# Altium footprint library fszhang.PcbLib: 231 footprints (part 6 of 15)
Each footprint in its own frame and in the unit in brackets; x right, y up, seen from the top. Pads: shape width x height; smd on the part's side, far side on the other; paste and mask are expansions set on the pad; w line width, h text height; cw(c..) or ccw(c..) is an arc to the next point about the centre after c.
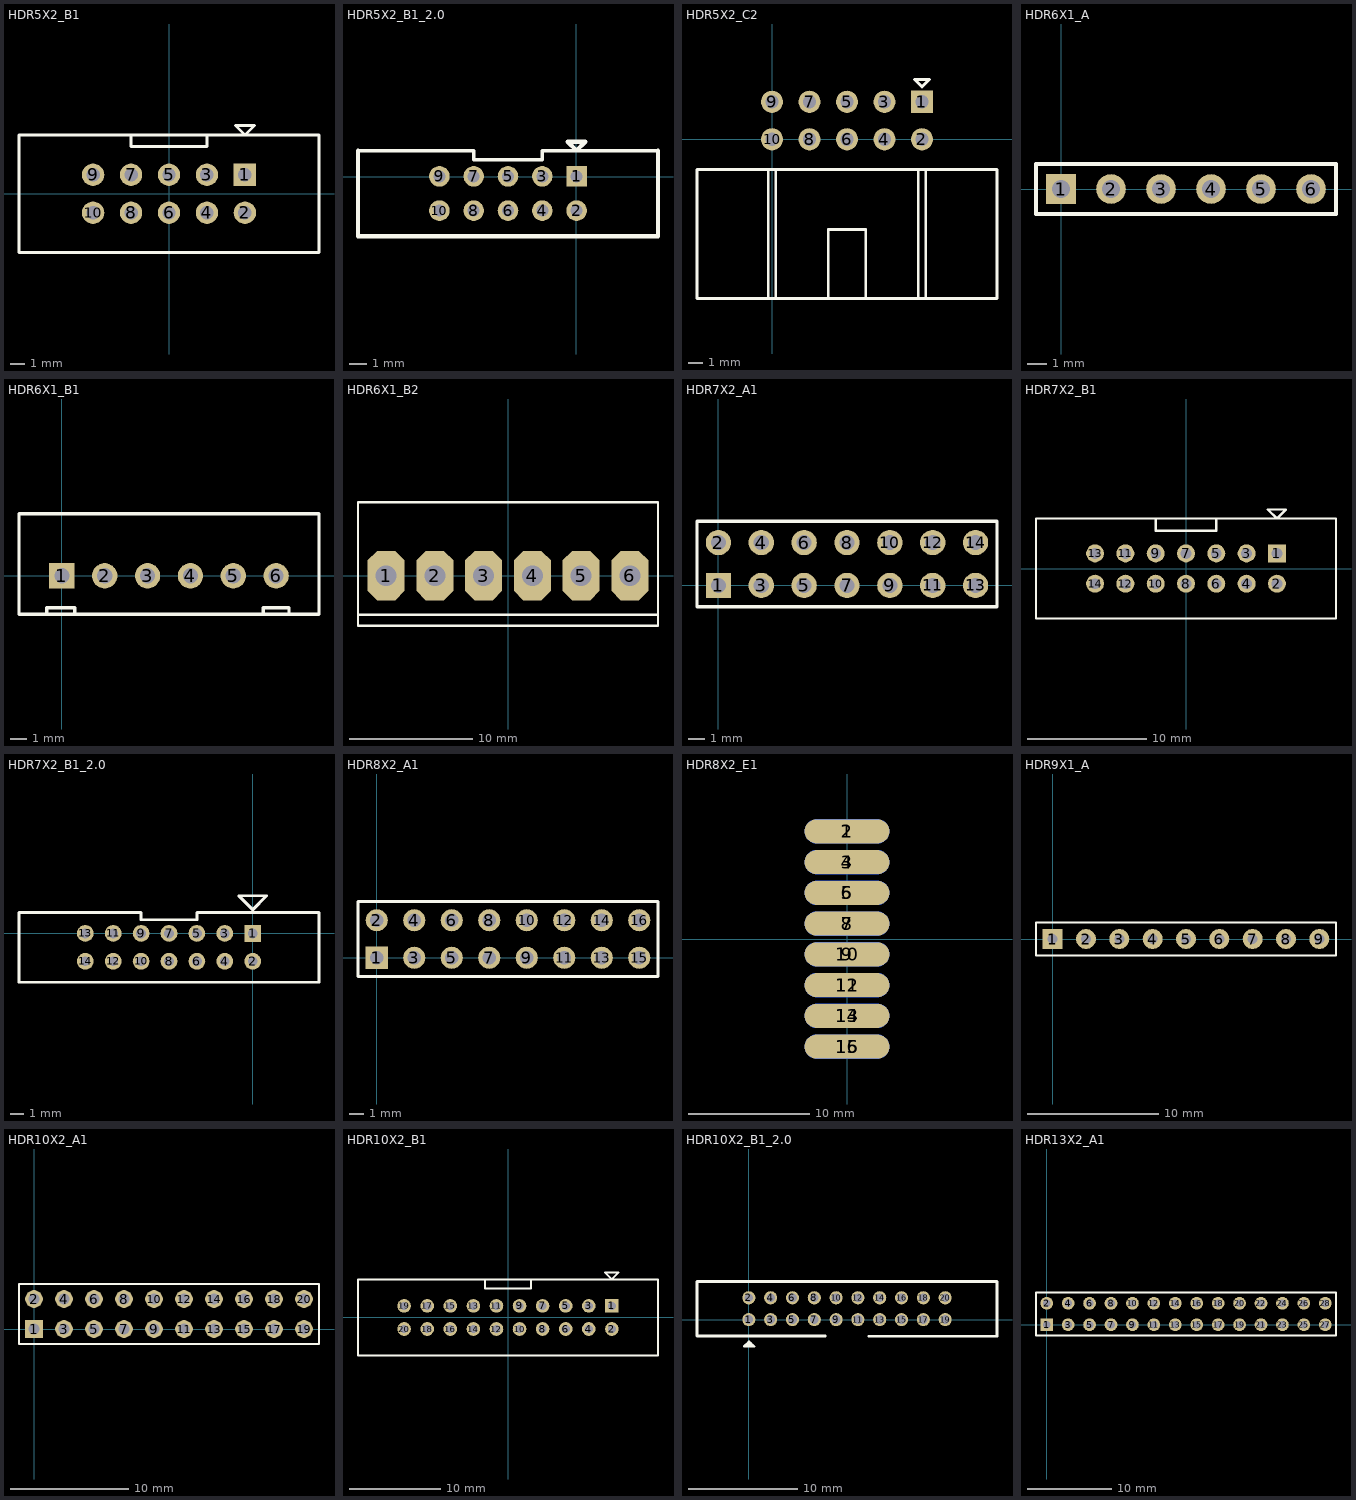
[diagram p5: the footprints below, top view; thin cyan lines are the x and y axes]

## HDR5X2_B1 [mm] "Connector; Header; 5x2 Position"
height 1.2
pads (10):
  rect 1.5x1.5 hole 0.9: 1(5.08,1.27)
  round 1.5 hole 0.9: 2(5.08,-1.27) 3(2.54,1.27) 4(2.54,-1.27) 5(0,1.27) 6(0,-1.27) 7(-2.54,1.27) 8(-2.54,-1.27) 9(-5.08,1.27) 10(-5.08,-1.27)
Top Overlay:
  lines w0.2: -2.54,3.937 -2.54,3.175 2.54,3.175 2.54,3.937 ; -10.033,-3.937 10.033,-3.937 10.033,3.937 -10.033,3.937 -10.033,-3.937 ; 4.445,4.572 5.588,4.572 5.715,4.572 5.08,3.937 4.445,4.572

## HDR5X2_B1_2.0 [mm]
pads (10):
  rect 1.2x1.2 hole 0.7: 1(0.006,0.012)
  round 1.2 hole 0.7: 2(0.006,-1.988) 3(-1.994,0.012) 4(-1.994,-1.988) 5(-3.994,0.012) 6(-3.994,-1.988) 7(-5.994,0.012) 8(-5.994,-1.988) 9(-7.994,0.012) 10(-7.994,-1.988)
Top Overlay:
  lines w0.2: -12.744,1.512 -5.994,1.512 -5.994,0.987 -1.994,0.987 -1.994,1.512 4.756,1.512
  lines w0.254: -12.744,1.512 -12.744,-3.488 4.756,-3.488 4.756,1.512 ; -0.508,2.032 0.508,2.032 0,1.524 -0.508,2.032

## HDR5X2_C2 [mm]
height 1.75
pads (10):
  rect 1.5x1.5 hole 0.9: 1(10.16,2.54)
  round 1.5 hole 0.9: 2(10.16,0) 3(7.62,2.54) 4(7.62,0) 5(5.08,2.54) 6(5.08,0) 7(2.54,2.54) 8(2.54,0) 9(0,2.54) 10(0,0)
Top Overlay:
  lines w0.2: -0.254,-10.795 -0.254,-2.032 ; 0.254,-10.795 0.254,-2.032 ; 3.81,-10.795 3.81,-6.096 6.35,-6.096 6.35,-10.795 ; 9.906,-10.795 9.906,-2.032 ; 10.414,-10.795 10.414,-2.032 ; -5.08,-10.795 -5.08,-2.032 15.24,-2.032 15.24,-10.795 -5.08,-10.795 ; 9.652,4.064 10.541,4.064 10.668,4.064 10.16,3.556 9.652,4.064

## HDR6X1_A [mm] "Connector; Header; 4 Position"
height 1.6
pads (6):
  rect 1.5x1.5 hole 0.9: 1(0,0)
  round 1.5 hole 0.9: 2(2.54,0) 3(5.08,0) 4(7.62,0) 5(10.16,0) 6(12.7,0)
Top Overlay:
  lines w0.2: -1.27,-1.27 -1.27,1.27 13.97,1.27 13.97,-1.27 -1.27,-1.27

## HDR6X1_B1 [mm] "Connector; Header; 4 Position"
height 1.6
pads (6):
  rect 1.5x1.5 hole 0.9: 1(0,0)
  round 1.5 hole 0.9: 2(2.54,0) 3(5.08,0) 4(7.62,0) 5(10.16,0) 6(12.7,0)
Top Overlay:
  lines w0.2: -0.889,-2.286 -0.889,-1.905 0.762,-1.905 0.762,-2.286 ; 11.938,-2.286 11.938,-1.905 13.462,-1.905 13.462,-2.286 ; -2.54,-2.286 15.24,-2.286 15.24,3.683 -2.54,3.683 -2.54,-2.286
3D body: height 1.5, standoff 0, extent -2.413,-2.159 15.24,3.556

## HDR6X1_B2 [mm] "Connector; Header; 3 Position"
height 1.5
pads (6):
  oct 3x4 hole 1.7: 1(-9.906,0) 2(-5.944,0) 3(-1.981,0) 4(1.981,0) 5(5.944,0) 6(9.906,0)
Top Overlay:
  lines w0.2: -12.192,-3.175 12.192,-3.175 ; -2.54,-4.064 2.54,-4.064 ; -12.192,-4.064 -12.192,5.969 12.192,5.969 12.192,-4.064 -12.192,-4.064

## HDR7X2_A1 [mm] "Connector; Header; 7x2 Position"
height 1.75
pads (14):
  rect 1.5x1.5 hole 0.9: 1(0,0)
  round 1.5 hole 0.9: 2(0,2.54) 3(2.54,0) 4(2.54,2.54) 5(5.08,0) 6(5.08,2.54) 7(7.62,0) 8(7.62,2.54) 9(10.16,0) 10(10.16,2.54) 11(12.7,0) 12(12.7,2.54) 13(15.24,0) 14(15.24,2.54)
Top Overlay:
  lines w0.2: -1.27,-1.27 -1.27,3.81 16.51,3.81 16.51,-1.27 -1.27,-1.27

## HDR7X2_B1 [mm] "Connector"
height 2.65
pads (14):
  rect 1.5x1.5 hole 0.9: 1(7.62,1.27)
  round 1.5 hole 0.9: 2(7.62,-1.27) 3(5.08,1.27) 4(5.08,-1.27) 5(2.54,1.27) 6(2.54,-1.27) 7(0,1.27) 8(0,-1.27) 9(-2.54,1.27) 10(-2.54,-1.27) 11(-5.08,1.27) 12(-5.08,-1.27) 13(-7.62,1.27) 14(-7.62,-1.27)
Top Overlay:
  lines w0.2: -2.54,4.191 -2.54,3.175 2.54,3.175 2.54,4.191 ; -12.573,-4.191 12.573,-4.191 12.573,4.191 -12.573,4.191 -12.573,-4.191 ; 6.858,4.953 7.62,4.191 8.382,4.953 8.255,4.953 6.858,4.953

## HDR7X2_B1_2.0 [mm]
pads (14):
  rect 1.2x1.2 hole 0.7: 1(0,0)
  round 1.2 hole 0.7: 2(0,-2) 3(-2,0) 4(-2,-2) 5(-4,0) 6(-4,-2) 7(-6,0) 8(-6,-2) 9(-8,0) 10(-8,-2) 11(-10,0) 12(-10,-2) 13(-12,0) 14(-12,-2)
Top Overlay:
  lines w0.2: -16.75,-3.5 4.75,-3.5 4.75,1.5 -4,1.5 -4,0.975 -8,0.975 -8,1.5 -16.75,1.5 -16.75,-3.5 ; -1,2.7 1,2.7 0,1.7 -1,2.7

## HDR8X2_A1 [mm] "Connector; Header; 8x2 Position"
pads (16):
  rect 1.5x1.5 hole 0.9: 1(0,0)
  round 1.5 hole 0.9: 2(0,2.54) 3(2.54,0) 4(2.54,2.54) 5(5.08,0) 6(5.08,2.54) 7(7.62,0) 8(7.62,2.54) 9(10.16,0) 10(10.16,2.54) 11(12.7,0) 12(12.7,2.54) 13(15.24,0) 14(15.24,2.54) 15(17.78,0) 16(17.78,2.54)
Top Overlay:
  lines w0.2: -1.27,-1.27 -1.27,3.81 19.05,3.81 19.05,-1.27 -1.27,-1.27

## HDR8X2_E1 [mm]
pads (16):
  oval 7x2 smd: 1(0,8.89) 3(0,6.35) 5(0,3.81) 7(0,1.27) 9(0,-1.27) 11(0,-3.81) 13(0,-6.35) 15(0,-8.89)
  oval 7x2 smd far side: 2(0,8.89) 4(0,6.35) 6(0,3.81) 8(0,1.27) 10(0,-1.27) 12(0,-3.81) 14(0,-6.35) 16(0,-8.89)

## HDR9X1_A [mil] "2.54mm"
height 196.85
pads (9):
  rect 60x60 hole 30: 1(0,0)
  round 60 hole 30: 2(100,0) 3(200,0) 4(300,0) 5(400,0) 6(500,0) 7(600,0) 8(700,0) 9(800,0)
Top Overlay:
  lines w5.91: -50,-50 -50,50 850,50 850,-50 -50,-50

## HDR10X2_A1 [mm] "Connector; Header; 10x2 Position"
height 1.75
pads (20):
  rect 1.5x1.5 hole 0.9: 1(0,0)
  round 1.5 hole 0.9: 2(0,2.54) 3(2.54,0) 4(2.54,2.54) 5(5.08,0) 6(5.08,2.54) 7(7.62,0) 8(7.62,2.54) 9(10.16,0) 10(10.16,2.54) 11(12.7,0) 12(12.7,2.54) 13(15.24,0) 14(15.24,2.54) 15(17.78,0) 16(17.78,2.54) 17(20.32,0) 18(20.32,2.54) 19(22.86,0) 20(22.86,2.54)
Top Overlay:
  lines w0.2: -1.27,-1.27 0.635,-1.27 24.13,-1.27 24.13,3.81 0.635,3.81 -1.27,3.81 -1.27,-1.27

## HDR10X2_B1 [mm]
height 7
pads (20):
  rect 1.5x1.5 hole 0.9: 1(11.43,1.27)
  round 1.5 hole 0.9: 2(11.43,-1.27) 3(8.89,1.27) 4(8.89,-1.27) 5(6.35,1.27) 6(6.35,-1.27) 7(3.81,1.27) 8(3.81,-1.27) 9(1.27,1.27) 10(1.27,-1.27) 11(-1.27,1.27) 12(-1.27,-1.27) 13(-3.81,1.27) 14(-3.81,-1.27) 15(-6.35,1.27) 16(-6.35,-1.27) 17(-8.89,1.27) 18(-8.89,-1.27) 19(-11.43,1.27) 20(-11.43,-1.27)
Top Overlay:
  lines w0.2: -2.54,4.191 -2.54,3.175 2.54,3.175 2.54,4.191 ; -16.51,-4.191 16.51,-4.191 16.51,4.191 -16.51,4.191 -16.51,-4.191 ; 10.668,4.953 12.192,4.953 11.43,4.191 10.668,4.953

## HDR10X2_B1_2.0 [mm]
pads (20):
  round 1.2 hole 0.8: 1(-0.003,-0.008) 2(-0.003,1.992) 3(1.997,-0.008) 4(1.997,1.992) 5(3.997,-0.008) 6(3.997,1.992) 7(5.997,-0.008) 8(5.997,1.992) 9(7.997,-0.008) 10(7.997,1.992) 11(9.997,-0.008) 12(9.997,1.992) 13(11.997,-0.008) 14(11.997,1.992) 15(13.997,-0.008) 16(13.997,1.992) 17(15.997,-0.008) 18(15.997,1.992) 19(17.997,-0.008) 20(17.997,1.992)
Top Overlay:
  lines w0.2: 0.308,-2.294 -0.238,-2.294 -0.252,-2.281 0.103,-2.281 0.199,-2.185 0.199,-2.256 -0.028,-2.483 -0.028,-2.058 -0.003,-2.033 ; -0.003,-2.033 0.047,-2.033 0.497,-2.483 0.297,-2.483 -0.453,-2.483 -0.003,-2.033
  lines w0.254: 6.997,-1.508 -4.753,-1.508 -4.753,3.492 22.747,3.492 22.747,-1.508 ; 10.997,-1.533 22.747,-1.533

## HDR13X2_A1 [mm]
height 7
pads (28):
  rect 1.5x1.5 hole 0.9: 1(0,0)
  round 1.5 hole 0.9: 2(0,2.54) 3(2.54,0) 4(2.54,2.54) 5(5.08,0) 6(5.08,2.54) 7(7.62,0) 8(7.62,2.54) 9(10.16,0) 10(10.16,2.54) 11(12.7,0) 12(12.7,2.54) 13(15.24,0) 14(15.24,2.54) 15(17.78,0) 16(17.78,2.54) 17(20.32,0) 18(20.32,2.54) 19(22.86,0) 20(22.86,2.54) 21(25.4,0) 22(25.4,2.54) 23(27.94,0) 24(27.94,2.54) 25(30.48,0) 26(30.48,2.54) 27(33.02,0) 28(33.02,2.54)
Top Overlay:
  lines w0.2: -1.27,-1.27 34.29,-1.27 34.29,3.81 -1.27,3.81 -1.27,-1.27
